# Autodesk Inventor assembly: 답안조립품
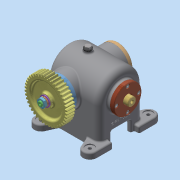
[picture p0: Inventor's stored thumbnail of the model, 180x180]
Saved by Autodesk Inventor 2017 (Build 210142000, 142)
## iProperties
Part Number: 답안조립품
Material: 일반
Document SubType Name: Assembly
Designer: MRC
Author: MRC
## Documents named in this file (17)
- C:\Users\MRC\Desktop\740904V1019\답안조립품.iam
- C:\Users\MRC\Desktop\공용부품_20240817_21231321\깊은 홈 볼베어링 6203.ipt
- C:\Users\MRC\Desktop\공용부품_20240817_21231321\뒷커버.ipt
- C:\Users\MRC\Desktop\공용부품_20240817_21231321\로드.ipt
- C:\Users\MRC\Desktop\공용부품_20240817_21231321\부시.ipt
- C:\Users\MRC\Desktop\공용부품_20240817_21231321\스퍼 기어.ipt
- C:\Users\MRC\Desktop\공용부품_20240817_21231321\스프링와셔 M10.ipt
- C:\Users\MRC\Desktop\공용부품_20240817_21231321\실링 패드.ipt
- C:\Users\MRC\Desktop\공용부품_20240817_21231321\앞커버.ipt
- C:\Users\MRC\Desktop\공용부품_20240817_21231321\오일실 17 32 8.ipt
- C:\Users\MRC\Desktop\공용부품_20240817_21231321\육각 너트 M10x1.ipt
- C:\Users\MRC\Desktop\공용부품_20240817_21231321\육각 머리 볼트 M6x0.75x12.ipt
- C:\Users\MRC\Desktop\공용부품_20240817_21231321\육각 소켓 머리 볼트 M4x10.ipt
- C:\Users\MRC\Desktop\공용부품_20240817_21231321\편심축.ipt
- C:\Users\MRC\Desktop\공용부품_20240817_21231321\평와셔 M10.ipt
- C:\Users\MRC\Desktop\공용부품_20240817_21231321\평행키 3x3x14.ipt
- C:\Users\MRC\Desktop\740904V1019\본체.ipt
